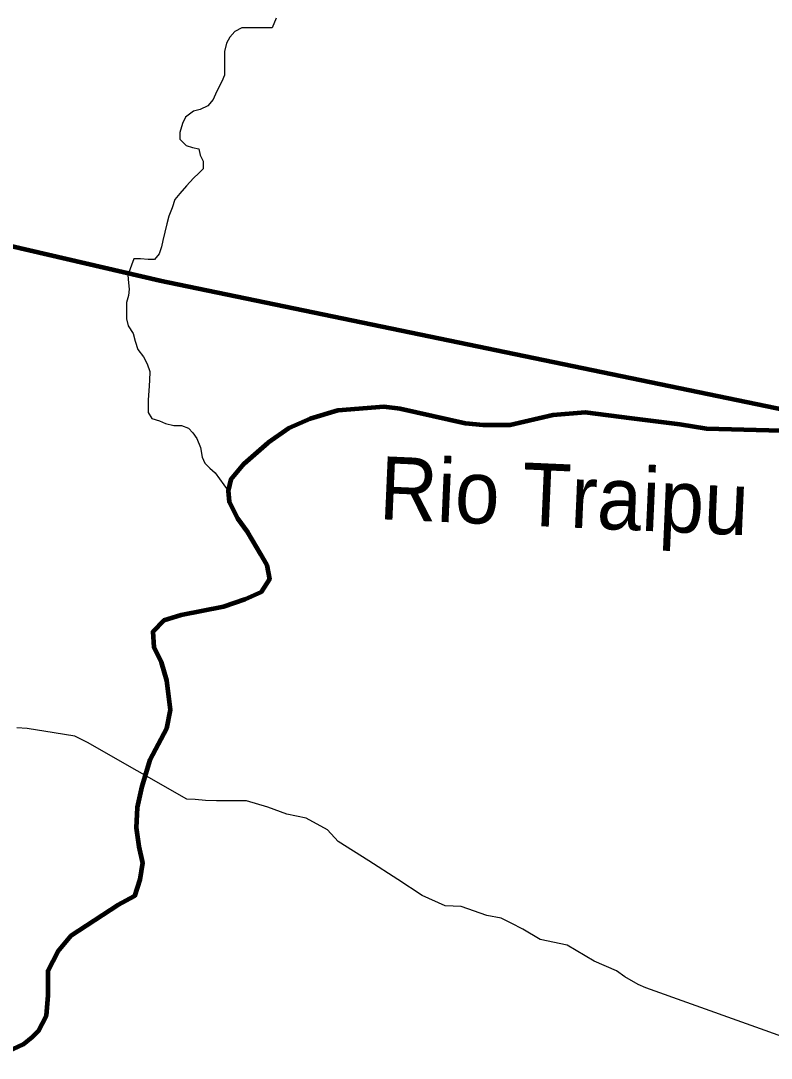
# Model space of a CAD drawing. Extents: x 553962 to 842807, y 8883888 to 9032388.
# Drawn here: x 723723 to 729677, y 8929936 to 8938163 of the extents above; entities that cross this region are included whole.
import ezdxf
from ezdxf.enums import TextEntityAlignment as Align

# ---------------------------------------------------------------- set-up
doc = ezdxf.new("R2010")
doc.units = 0
doc.header["$LTSCALE"] = 200
doc.linetypes.add('DASH_DOUBLE_DOT', pattern=[9.2, 5, -1.2, 0.3, -1.2, 0.3, -1.2])
for name, color, linetype, lineweight in [('11', 7, 'DASH_DOUBLE_DOT', 106), ('12', 7, 'Continuous', 25), ('24', 7, 'Continuous', 25), ('9', 7, 'Continuous', 90)]:
    doc.layers.add(name, color=color, linetype=linetype, lineweight=lineweight)
doc.layers.add('49', color=7, linetype='Continuous')

msp = doc.modelspace()

# ---------------------------------------------------------------- linework, layer by layer
at = {"layer": '11'}
for points in [[(726733.4, 8935086.7), (726602, 8935101.3), (726237.1, 8935072), (726018.1, 8935006.3), (725850.2, 8934933.2), (725682.3, 8934816.3), (725492.6, 8934648.3), (725390.4, 8934524.1), (725368.5, 8934436.4), (725375.8, 8934348.7), (725441.5, 8934217.2), (725521.8, 8934107.6), (725624, 8933932.2), (725675.1, 8933844.6), (725697, 8933734.9), (725631.3, 8933632.7), (725499.9, 8933574.2), (725332, 8933515.8), (724996.3, 8933450), (724857.6, 8933406.2), (724770, 8933318.5), (724777.3, 8933194.3), (724835.7, 8933077.4), (724879.5, 8932931.2), (724908.7, 8932697.4), (724879.5, 8932551.3), (724748.1, 8932302.9), (724682.4, 8932091), (724645.9, 8931922.9), (724638.6, 8931762.2), (724660.5, 8931616.1), (724689.7, 8931484.6), (724667.8, 8931353), (724624, 8931221.5), (724492.7, 8931148.4), (724120.4, 8930907.3), (724018.2, 8930783.1)], [(729755, 8934911.3), (729163.8, 8934925.9), (728952.2, 8934962.4), (728571.5, 8935009.7), (728200.4, 8935057.4), (727944.9, 8935035.5), (727601.9, 8934955.1), (727390.2, 8934955.1), (727251.6, 8934969.8), (726733.4, 8935086.7)], [(724018.2, 8930783.1), (723938, 8930629.7), (723938, 8930432.4), (723924.2, 8930271.2), (723861.2, 8930151.4), (723813.9, 8930103.6), (723741.7, 8930044.3), (723507.3, 8929935.6)]]:
    msp.add_lwpolyline(points, dxfattribs=at)
at = {"layer": '12'}
msp.add_lwpolyline([(729842.6, 8930080), (728682.6, 8930494.7), (728621.5, 8930520.3), (728514.8, 8930581.6), (728448.7, 8930627.6), (728270.7, 8930704.3), (728057.2, 8930832.1), (727843.4, 8930878.3), (727706.2, 8930960.1), (727614.7, 8931006.1), (727533.3, 8931047), (727421.3, 8931067.6), (727217.8, 8931139.3), (727090.4, 8931144.6), (726907.3, 8931226.4), (726714.2, 8931354.1), (726485.5, 8931502.3), (726241.6, 8931655.6), (726155.3, 8931747.4), (725987.5, 8931839.4), (725834.8, 8931870.3), (725682.2, 8931926.6), (725514.3, 8931977.8), (725392, 8931978.1), (725274.8, 8931978.3), (725188.2, 8931978.4), (725106.8, 8931988.8), (725040.5, 8931988.9), (724252.6, 8932438.6), (724150.9, 8932489.8), (723987.9, 8932515.5), (723774.1, 8932551.6), (723692.6, 8932556.8)], dxfattribs=at)
at = {"layer": '24'}
for points in [[(725748, 8938182.8), (725717, 8938106.6), (725544.1, 8938107.6), (725478, 8938108), (725421.8, 8938077.8), (725380.8, 8938032.2), (725355.1, 8937986.6), (725339.3, 8937920.5), (725339, 8937869.5), (725338.6, 8937818.6), (725338, 8937732.1), (725317.3, 8937681.2), (725276.1, 8937600), (725250.2, 8937539.1), (725207.8, 8937489.4), (725146.5, 8937460.6), (725092.5, 8937446.2), (725030.6, 8937397.8), (725004.8, 8937347.1), (724984, 8937275.9), (724983.6, 8937225), (725034.1, 8937173.8), (725084.8, 8937158.2), (725135.6, 8937147.7), (725145.5, 8937096.7), (725170.6, 8937050.7), (725170.1, 8936989.6), (725134.3, 8936954.2), (725093.3, 8936913.7), (725037, 8936852.9), (724985.7, 8936792.1), (724944.7, 8936746.5), (724923.9, 8936680.5), (724898, 8936614.4), (724882.3, 8936553.4), (724866.6, 8936487.3), (724850.9, 8936421.2), (724840.4, 8936370.3), (724819.6, 8936314.4), (724783.7, 8936268.8), (724732.8, 8936269.1), (724671.9, 8936274.6), (724621, 8936274.9)], [(724621, 8936274.9), (724573, 8936146.7), (724577.7, 8936085.6), (724582.4, 8936034.6), (724577, 8935983.7), (724561.3, 8935927.8), (724561, 8935876.9), (724560.4, 8935800.5), (724575.3, 8935744.4), (724615.6, 8935683), (724630.4, 8935621.8), (724650.3, 8935555.5), (724695.7, 8935499.2), (724725.8, 8935443), (724745.7, 8935381.8), (724745.2, 8935310.5), (724739.6, 8935229), (724734, 8935157.8), (724733.7, 8935106.9), (724733.3, 8935055.9), (724763.5, 8935009.9), (724824.4, 8934989.2), (724870, 8934968.5), (724936, 8934952.8), (724997.1, 8934952.5), (725052.8, 8934931.8), (725088.2, 8934895.9), (725118.4, 8934849.9), (725148.4, 8934778.4), (725163.2, 8934701.9), (725183.2, 8934656), (725223.6, 8934615), (725264, 8934579.1), (725368.5, 8934436.4)]]:
    msp.add_lwpolyline(points, dxfattribs=at)
at = {"layer": '24', "lineweight": 53}
for points in [[(726733.4, 8935086.7), (726602, 8935101.3), (726237.1, 8935072), (726018.1, 8935006.3), (725850.2, 8934933.2), (725682.3, 8934816.3), (725492.6, 8934648.3), (725390.4, 8934524.1), (725368.5, 8934436.4), (725375.8, 8934348.7), (725441.5, 8934217.2), (725521.8, 8934107.6), (725624, 8933932.2), (725675.1, 8933844.6), (725697, 8933734.9), (725631.3, 8933632.7), (725499.9, 8933574.2), (725332, 8933515.8), (724996.3, 8933450), (724857.6, 8933406.2), (724770, 8933318.5), (724777.3, 8933194.3), (724835.7, 8933077.4), (724879.5, 8932931.2), (724908.7, 8932697.4), (724879.5, 8932551.3), (724748.1, 8932302.9), (724682.4, 8932091), (724645.9, 8931922.9), (724638.6, 8931762.2), (724660.5, 8931616.1), (724689.7, 8931484.6), (724667.8, 8931353), (724624, 8931221.5), (724492.7, 8931148.4), (724120.4, 8930907.3), (724018.2, 8930783.1)], [(729755, 8934911.3), (729163.8, 8934925.9), (728952.2, 8934962.4), (728571.5, 8935009.7), (728200.4, 8935057.4), (727944.9, 8935035.5), (727601.9, 8934955.1), (727390.2, 8934955.1), (727251.6, 8934969.8), (726733.4, 8935086.7)], [(724018.2, 8930783.1), (723938, 8930629.7), (723938, 8930432.4), (723924.2, 8930271.2), (723861.2, 8930151.4), (723813.9, 8930103.6), (723741.7, 8930044.3), (723507.3, 8929935.6)]]:
    msp.add_lwpolyline(points, dxfattribs=at)
at = {"layer": '9'}
for points in [[(696242, 8937672.8), (702061.8, 8937200.5), (702208.9, 8933124.7), (710319.1, 8936704.6), (716154, 8938115.2), (724825.2, 8936103.1), (730092.7, 8935013.9)], [(726733.4, 8935086.7), (726602, 8935101.3), (726237.1, 8935072), (726018.1, 8935006.3), (725850.2, 8934933.2), (725682.3, 8934816.3), (725492.6, 8934648.3), (725390.4, 8934524.1), (725368.5, 8934436.4), (725375.8, 8934348.7), (725441.5, 8934217.2), (725521.8, 8934107.6), (725624, 8933932.2), (725675.1, 8933844.6), (725697, 8933734.9), (725631.3, 8933632.7), (725499.9, 8933574.2), (725332, 8933515.8), (724996.3, 8933450), (724857.6, 8933406.2), (724770, 8933318.5), (724777.3, 8933194.3), (724835.7, 8933077.4), (724879.5, 8932931.2), (724908.7, 8932697.4), (724879.5, 8932551.3), (724748.1, 8932302.9), (724682.4, 8932091), (724645.9, 8931922.9), (724638.6, 8931762.2), (724660.5, 8931616.1), (724689.7, 8931484.6), (724667.8, 8931353), (724624, 8931221.5), (724492.7, 8931148.4), (724120.4, 8930907.3), (724018.2, 8930783.1)], [(729755, 8934911.3), (729163.8, 8934925.9), (728952.2, 8934962.4), (728571.5, 8935009.7), (728200.4, 8935057.4), (727944.9, 8935035.5), (727601.9, 8934955.1), (727390.2, 8934955.1), (727251.6, 8934969.8), (726733.4, 8935086.7)], [(724018.2, 8930783.1), (723938, 8930629.7), (723938, 8930432.4), (723924.2, 8930271.2), (723861.2, 8930151.4), (723813.9, 8930103.6), (723741.7, 8930044.3), (723507.3, 8929935.6)]]:
    msp.add_lwpolyline(points, dxfattribs=at)

# ---------------------------------------------------------------- texts
at = {"layer": '49', "width": 0.95}
msp.add_text('Rio Traipu', height=500, rotation=357.482, dxfattribs=at).set_placement((728023.7, 8934146.6), align=Align.CENTER)

doc.saveas('drawing.dxf')
